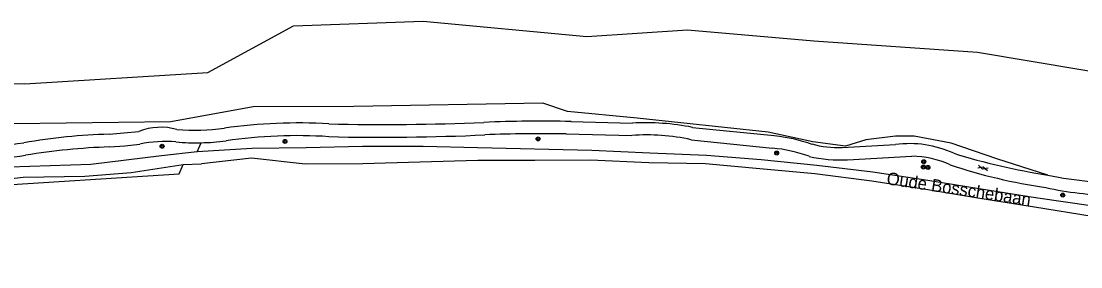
# Model space of a CAD drawing. Extents: x 137000 to 140001, y 403500 to 406000.
# Drawn here: x 138031.2 to 138245, y 405748.4 to 405797.9 of the extents above; entities that cross this region are included whole.
import ezdxf

# ---------------------------------------------------------------- set-up
doc = ezdxf.new("R2010")
doc.units = 0
for name, color, linetype in [('gg-afsc-draadraster', 7, 'Continuous'), ('gg-afsc-lijn draadraster', 7, 'Continuous'), ('gg-anno-openbare ruimte label', 7, 'Continuous'), ('gg-knt-onverhard', 7, 'Continuous'), ('gg-knt-verharding', 7, 'Continuous'), ('gt-grn-groengrens', 7, 'Continuous'), ('gt-symb-boom', 7, 'Continuous'), ('gt-symb-gesloten verharding', 7, 'Continuous')]:
    doc.layers.add(name, color=color, linetype=linetype)

# ---------------------------------------------------------------- blocks, each defined once
blk = doc.blocks.new('gt0-BOOM')
at = {"layer": 'gt-symb-boom'}
for radius in [0.4, 0.2]:
    blk.add_circle((0, 0), radius, dxfattribs=at)
blk = doc.blocks.new('gt0-GESVH1')
at = {"layer": 'gt-symb-gesloten verharding'}
for p, q in [((-0.99, -0.26), (0.01, 0.24)), ((0.01, -0.26), (-0.99, 0.24)), ((0.01, 0.24), (1.01, -0.26)), ((1.01, 0.24), (0.01, -0.26))]:
    blk.add_line(p, q, dxfattribs=at)

msp = doc.modelspace()

# ---------------------------------------------------------------- linework, layer by layer
at = {"layer": 'gg-afsc-draadraster'}
msp.add_lwpolyline([(138022.98, 405764.54), (138063.07, 405767.08), (138063.88, 405768.96)], dxfattribs=at)
at = {"layer": 'gg-afsc-lijn draadraster'}
msp.add_lwpolyline([(138022.98, 405764.54), (138063.07, 405767.08), (138063.88, 405768.96)], dxfattribs=at)
at = {"layer": 'gg-knt-onverhard'}
msp.add_line((138063.88, 405768.96), (138067.55, 405769.1), dxfattribs=at)
for points in [[(138298.71, 405748.38), (138291.67, 405750.67), (138280.55, 405753.44), (138269.75, 405756.04), (138258.71, 405758.6), (138247.55, 405760.57), (138235.93, 405762.25), (138224.91, 405763.99), (138214.16, 405765.74), (138203.06, 405767.46), (138191.74, 405768.79), (138180.55, 405769.9), (138169.49, 405770.78), (138158.07, 405771.24), (138146.37, 405771.82), (138123.29, 405772.35), (138112.32, 405772.64), (138100.04, 405772.6), (138088.68, 405772.36), (138077.76, 405772.23), (138066.69, 405771.54)], [(138066.69, 405771.54), (138059.51, 405770.72), (138045.24, 405769.02), (138024.67, 405768.35), (138015.96, 405766.83), (138005.82, 405764.4), (138000, 405763.44)], [(138022.93, 405765.28), (138025.72, 405765.77), (138031.6, 405766.41), (138044.05, 405766.62), (138053.4, 405767.4), (138063.88, 405768.96)], [(138285.29, 405750.05), (138280.52, 405751.41), (138258.08, 405756.52), (138247.37, 405758.48), (138235.71, 405760.38), (138224.67, 405762.12), (138213.74, 405763.92), (138202.85, 405765.65), (138191.37, 405767.11), (138180.28, 405768.09), (138169.32, 405769.1), (138157.83, 405769.33), (138146.06, 405769.86), (138134.82, 405769.79), (138123.36, 405769.77), (138111.63, 405769.44), (138100.16, 405769.1), (138088.48, 405769.03), (138077.67, 405770.26), (138067.55, 405769.1)]]:
    msp.add_lwpolyline(points, dxfattribs=at)
at = {"layer": 'gg-knt-verharding'}
for p, q in [((138142.15, 405777.65), (138154.57, 405777.34)), ((138141.19, 405775.14), (138154.4, 405774.84)), ((138166.39, 405773.99), (138182.81, 405772.26)), ((138196.89, 405772.44), (138207.63, 405773)), ((138197.97, 405769.95), (138210.94, 405770.67))]:
    msp.add_line(p, q, dxfattribs=at)
for points in [[(138048.93, 405775.1), (138051.92, 405775.34), (138054.91, 405775.67)], [(138166.67, 405776.47), (138183.15, 405774.81), (138184.25, 405774.68), (138185.35, 405774.52), (138186.99, 405774.2), (138188.61, 405773.79), (138189.67, 405773.47), (138190.73, 405773.12)], [(138049.03, 405772.54), (138052.08, 405772.76), (138055.12, 405773.11)]]:
    msp.add_lwpolyline(points, dxfattribs=at)
for centre, radius, start, end in [((138086.98, 405670.3), 107.06, 86.6193, 97.9282), ((138104.41, 406242.55), 465.51, 268.6311, 272.4796), ((138135.9, 405531.02), 246.71, 88.5482, 92.6367), ((138157.1, 405728), 49.41, 78.8347, 92.9423), ((138052.51, 405653.01), 122.14, 91.6786, 99.7921), ((138059.33, 405764.3), 12.19, 74.3583, 111.2434), ((138066.19, 405817.46), 41.57, 265.0634, 278.3267), ((138086.91, 405675.51), 99.29, 86.3198, 98.3309), ((138103.92, 406227.47), 452.99, 268.655, 272.6373), ((138135.67, 405527.84), 247.36, 88.7206, 92.5277), ((138157.51, 405733.65), 41.3, 77.583, 94.3165), ((138016.74, 405875.91), 103.63, 272.5199, 278.3183), ((138054.2, 405635.08), 137.56, 92.1557, 99.2541), ((138060.3, 405747.66), 25.97, 85.3298, 101.5099), ((138066.5, 405818.53), 45.17, 264.8178, 271.2433), ((138066.49, 405818.96), 45.6, 271.237, 277.6003), ((138195.89, 405791.76), 19.34, 254.5146, 272.9763), ((138210.5, 405751.68), 21.51, 65.5376, 97.6452), ((138018.36, 405860.82), 91.01, 272.7473, 278.6727), ((138180.68, 405744.77), 27.57, 69.7781, 85.5728), ((138196.47, 405796.99), 27.09, 256.6386, 273.1618), ((138210.56, 405751.04), 19.63, 65.5252, 88.9046), ((138257.78, 405893.58), 128.2, 252.5818, 261.3079), ((138254.39, 405876.67), 113.52, 251.6725, 261.6808), ((138253.63, 405838.54), 73.28, 258.011, 271.4201), ((138252.79, 405832.12), 69.38, 257.6621, 268.9163)]:
    msp.add_arc(centre, radius, start, end, dxfattribs=at)
at = {"layer": 'gt-grn-groengrens'}
msp.add_line((138066.69, 405771.54), (138067.48, 405773.37), dxfattribs=at)
for points in [[(137995.68, 405785.35), (138031.93, 405785.22), (138068.86, 405787.53), (138086.12, 405796.9), (138112.29, 405797.86), (138145.37, 405794.77), (138165.69, 405796.14), (138191.14, 405793.89), (138224.22, 405791.62), (138255.86, 405786.31)], [(138238.41, 405766.86), (138228.07, 405770.16), (138218.89, 405773.32), (138211.44, 405774.67), (138207.67, 405774.73), (138201.66, 405773.97), (138197.54, 405772.69), (138190.96, 405773.56), (138181.92, 405775.5), (138155.52, 405778.33), (138141.44, 405779.64), (138136.48, 405781.33), (138098.35, 405780.69), (138078.03, 405780.62), (138061.41, 405777.57), (138029.67, 405777.15)]]:
    msp.add_lwpolyline(points, dxfattribs=at)

# ---------------------------------------------------------------- block references
at = {"layer": 'gt-symb-boom'}
for p in [(138059.62, 405772.67), (138084.43, 405773.63), (138135.52, 405774.16), (138183.66, 405771.3), (138213.28, 405768.48), (138213.36, 405769.55), (138214.19, 405768.39), (138241.4, 405762.82)]:
    msp.add_blockref('gt0-BOOM', p, dxfattribs=at)
at = {"layer": 'gt-symb-gesloten verharding', "rotation": -16.024109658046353}
msp.add_blockref('gt0-GESVH1', (138225.29, 405768.32), dxfattribs=at)

# ---------------------------------------------------------------- texts
at = {"layer": 'gg-anno-openbare ruimte label'}
msp.add_text('Oude Bosschebaan', height=2.5, rotation=351.4, dxfattribs=at).set_placement((138205.73, 405765.02))

doc.saveas('drawing.dxf')
